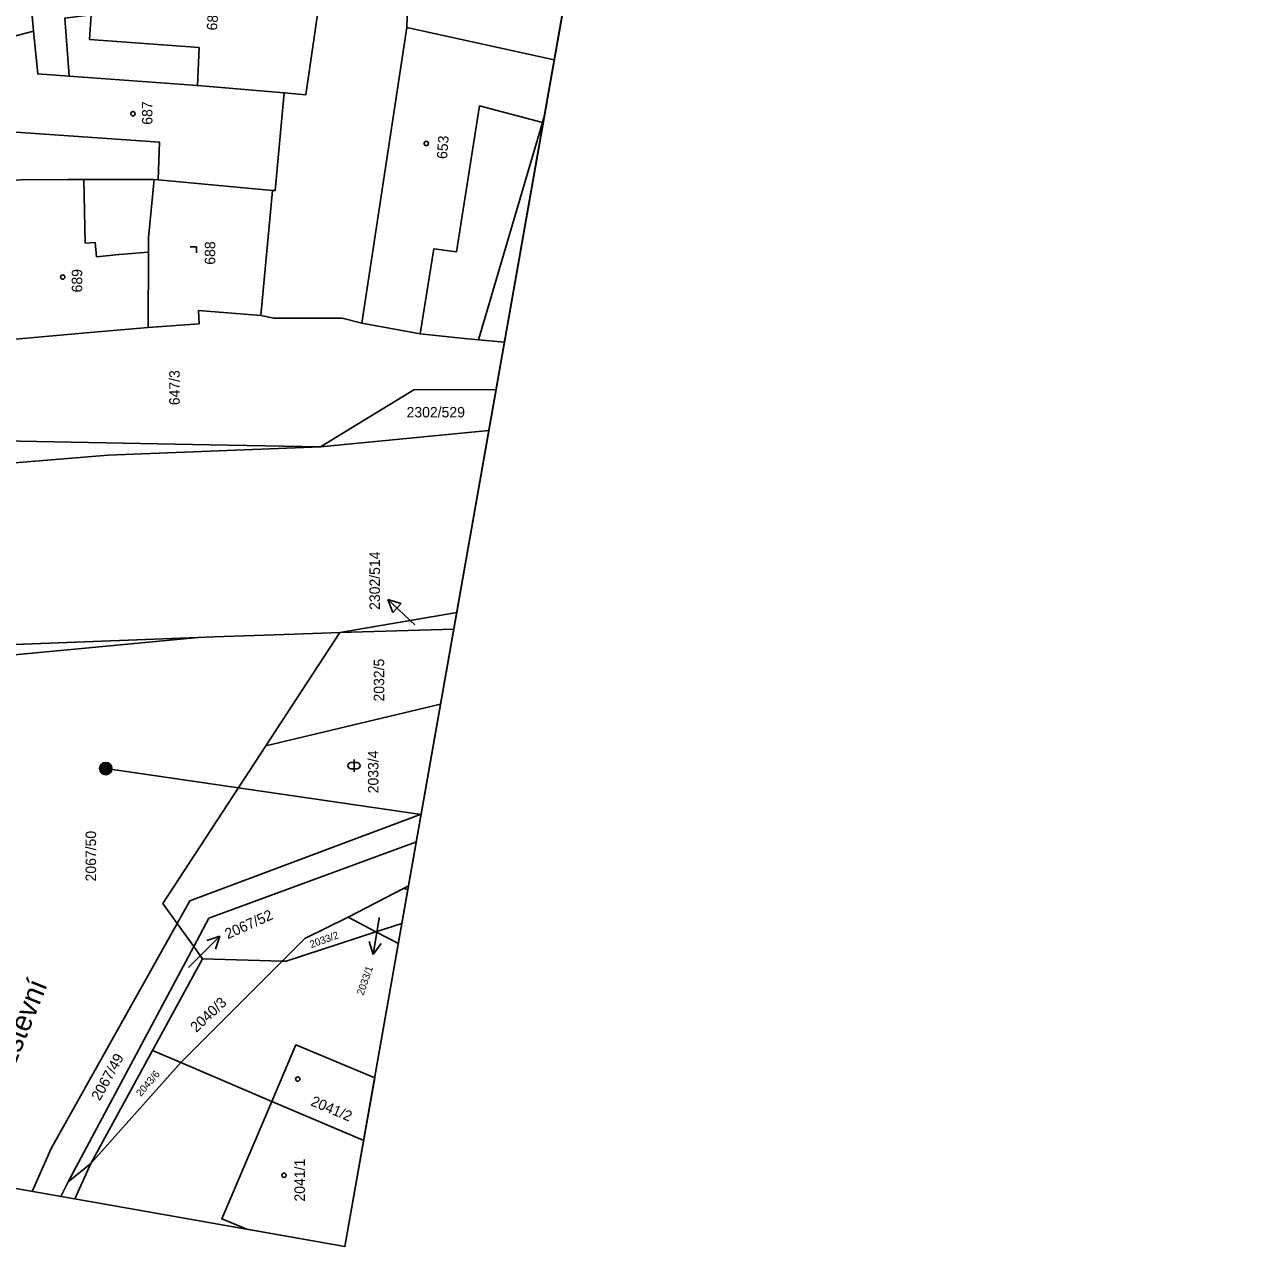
# Model space of a CAD drawing. Extents: x -534481 to -534262, y -1190577 to -1190138.
# Drawn here: x -534360.6 to -534261.7, y -1190577.1 to -1190477.8 of the extents above; entities that cross this region are included whole.
import ezdxf

# ---------------------------------------------------------------- set-up
doc = ezdxf.new("R2010")
doc.units = 0
for name, color, linetype in [('_KN_Povodí_Moravy', 7, 'Continuous'), ('_rámeček', 7, 'Continuous'), ('_rámeček_mřížka', 7, 'Continuous'), ('Hranice parcel', 7, 'Continuous'), ('Parcelní čísla', 7, 'Continuous'), ('Polygon budovy', 7, 'Continuous'), ('Pop  PČ popisy', 7, 'Continuous'), ('Poz předměty', 7, 'Continuous'), ('Značky budov', 7, 'Continuous'), ('Značky kultur', 7, 'Continuous')]:
    doc.layers.add(name, color=color, linetype=linetype)

msp = doc.modelspace()

# ---------------------------------------------------------------- linework, layer by layer
at = {"layer": '_KN_Povodí_Moravy'}
for p, q in [((-534322.907, -1190510.761), (-534336.58, -1190512.09)), ((-534325.515, -1190525.554), (-534322.907, -1190510.761)), ((-534330.718, -1190525.556), (-534331.106, -1190524.506)), ((-534331.106, -1190524.506), (-534330.033, -1190524.825)), ((-534330.376, -1190525.19), (-534330.375, -1190525.191)), ((-534381.269, -1190528.899), (-534346.53, -1190527.59))]:
    msp.add_line(p, q, dxfattribs=at)
for points in [[(-534336.58, -1190512.09), (-534345.56, -1190512.439), (-534353.84, -1190512.76), (-534368.41, -1190513.97)], [(-534330.375, -1190525.191), (-534330.718, -1190525.556)], [(-534330.033, -1190524.825), (-534330.376, -1190525.19)], [(-534335.01, -1190527.19), (-534329.294, -1190526.205), (-534328.987, -1190526.152), (-534325.515, -1190525.554)], [(-534346.53, -1190527.59), (-534345.23, -1190527.54), (-534338.73, -1190527.32), (-534335.01, -1190527.19)]]:
    msp.add_lwpolyline(points, dxfattribs=at)
at = {"layer": '_rámeček'}
for points in [[(-534407.912, -1190137.674), (-534480.845, -1190551.293), (-534334.601, -1190577.08), (-534261.668, -1190163.461)], [(-534480.845, -1190551.293), (-534334.601, -1190577.08), (-534316.367, -1190473.675)]]:
    msp.add_lwpolyline(points, dxfattribs=at)
at = {"layer": '_rámeček_mřížka'}
msp.add_lwpolyline([(-534480.845, -1190551.293), (-534334.601, -1190577.08), (-534261.668, -1190163.461)], dxfattribs=at)
at = {"layer": 'Hranice parcel'}
for p, q in [((-534360.35, -1190473.34), (-534359.92, -1190478.31)), ((-534359.92, -1190478.31), (-534363.23, -1190479.17)), ((-534329.58, -1190478.02), (-534333.24, -1190502.03)), ((-534317.593, -1190480.628), (-534329.58, -1190478.02)), ((-534318.55, -1190485.72), (-534318.46, -1190485.43)), ((-534318.411, -1190485.262), (-534318.46, -1190485.43)), ((-534323.74, -1190503.39), (-534318.55, -1190485.72)), ((-534340.49, -1190491.25), (-534341.45, -1190501.42)), ((-534323.74, -1190503.39), (-534321.639, -1190503.572)), ((-534335.01, -1190527.19), (-534341.03, -1190536.4)), ((-534346.53, -1190527.59), (-534363.09, -1190529.14)), ((-534341.03, -1190536.4), (-534326.83, -1190533.01)), ((-534341.03, -1190536.4), (-534349.4, -1190549.21)), ((-534329.84, -1190547.99), (-534334.33, -1190550.31)), ((-534329.485, -1190548.07), (-534329.84, -1190547.99)), ((-534349.4, -1190549.21), (-534348.24, -1190550.82)), ((-534348.24, -1190550.82), (-534346.89, -1190552.7)), ((-534332.09, -1190551.51), (-534334.33, -1190550.31)), ((-534329.971, -1190550.826), (-534332.09, -1190551.51)), ((-534332.09, -1190551.51), (-534330.259, -1190552.46)), ((-534357.1, -1190571.82), (-534346.89, -1190552.7)), ((-534346.89, -1190552.7), (-534346.17, -1190553.69)), ((-534346.17, -1190553.69), (-534350.25, -1190561.15)), ((-534339.7, -1190553.88), (-534347.95, -1190562.13)), ((-534346.17, -1190553.69), (-534339.7, -1190553.88)), ((-534350.25, -1190561.15), (-534355.26, -1190570.33)), ((-534347.95, -1190562.13), (-534350.25, -1190561.15)), ((-534347.95, -1190562.13), (-534355.26, -1190570.33)), ((-534340.55, -1190565.28), (-534347.95, -1190562.13)), ((-534333.081, -1190568.462), (-534340.55, -1190565.28)), ((-534355.26, -1190570.33), (-534357.1, -1190571.82)), ((-534355.26, -1190570.33), (-534356.54, -1190573.212)), ((-534357.68, -1190573.011), (-534357.1, -1190571.82))]:
    msp.add_line(p, q, dxfattribs=at)
for points in [[(-534329.58, -1190478.02), (-534329.52, -1190476.22), (-534329.36, -1190471.67), (-534329.3, -1190469.99)], [(-534336.54, -1190474.87), (-534337.79, -1190483.49), (-534339.53, -1190483.31)], [(-534359.92, -1190478.31), (-534359.56, -1190481.78), (-534357.01, -1190481.97), (-534346.59, -1190482.73), (-534339.53, -1190483.31)], [(-534339.53, -1190483.31), (-534340.26, -1190491.25), (-534340.49, -1190491.25)], [(-534318.46, -1190485.43), (-534318.442, -1190485.438)], [(-534360.94, -1190490.38), (-534357.12, -1190490.37), (-534355.82, -1190490.37), (-534352.77, -1190490.36), (-534350.1, -1190490.36)], [(-534350.1, -1190490.36), (-534350.56, -1190495.07), (-534350.57, -1190496.27), (-534350.6, -1190502.38)], [(-534350.1, -1190490.36), (-534349.79, -1190490.39), (-534340.49, -1190491.25)], [(-534350.6, -1190502.38), (-534346.45, -1190502.08), (-534346.49, -1190501), (-534341.45, -1190501.42)], [(-534341.45, -1190501.42), (-534340.38, -1190501.64), (-534334.84, -1190501.63), (-534333.24, -1190502.03)], [(-534361.66, -1190503.37), (-534355.33, -1190502.8), (-534350.6, -1190502.38)], [(-534333.24, -1190502.03), (-534328.48, -1190502.91), (-534324.65, -1190503.31), (-534323.74, -1190503.39)], [(-534336.58, -1190512.09), (-534329.01, -1190507.46), (-534322.321, -1190507.441)], [(-534372.58, -1190511.69), (-534370.92, -1190511.44), (-534345.58, -1190511.92), (-534336.58, -1190512.09)], [(-534322.907, -1190510.761), (-534336.58, -1190512.09)], [(-534336.58, -1190512.09), (-534353.84, -1190512.76), (-534368.41, -1190513.97)], [(-534335.01, -1190527.19), (-534325.515, -1190525.554)], [(-534346.53, -1190527.59), (-534345.23, -1190527.54), (-534338.73, -1190527.32), (-534335.01, -1190527.19)], [(-534325.756, -1190526.92), (-534335.01, -1190527.19)], [(-534381.269, -1190528.899), (-534346.53, -1190527.59)], [(-534348.24, -1190550.82), (-534347.22, -1190548.99), (-534328.402, -1190541.928)], [(-534346.89, -1190552.7), (-534345.66, -1190550.4), (-534328.801, -1190544.189)], [(-534329.431, -1190547.763), (-534329.84, -1190547.99)], [(-534348.24, -1190550.82), (-534358.48, -1190569.12), (-534360.013, -1190572.599)], [(-534334.33, -1190550.31), (-534337.86, -1190552.04), (-534339.7, -1190553.88)], [(-534332.09, -1190551.51), (-534339.39, -1190553.89), (-534339.7, -1190553.88)], [(-534332.182, -1190563.363), (-534338.6, -1190560.69), (-534340.55, -1190565.28)], [(-534340.55, -1190565.28), (-534344.61, -1190574.82), (-534342.564, -1190575.676)]]:
    msp.add_lwpolyline(points, dxfattribs=at)
at = {"layer": 'Polygon budovy'}
msp.add_line((-534318.411, -1190485.262), (-534317.593, -1190480.628), dxfattribs=at)
for points in [[(-534360.35, -1190473.34), (-534359.92, -1190478.31), (-534359.56, -1190481.78), (-534357.01, -1190481.97), (-534357.36, -1190477.25), (-534355.22, -1190476.99), (-534355.37, -1190478.98), (-534346.45, -1190479.65), (-534346.59, -1190482.73), (-534339.53, -1190483.31), (-534337.79, -1190483.49), (-534336.54, -1190474.87), (-534344.1, -1190474.27), (-534347.75, -1190473.84), (-534350.15, -1190473.56), (-534350.19, -1190473.9)], [(-534361.82, -1190486.07), (-534361.73, -1190486.49), (-534349.66, -1190487.33), (-534349.79, -1190490.39), (-534340.49, -1190491.25), (-534340.26, -1190491.25), (-534339.53, -1190483.31), (-534346.59, -1190482.73), (-534357.01, -1190481.97), (-534359.56, -1190481.78), (-534359.92, -1190478.31), (-534363.23, -1190479.17)], [(-534361.66, -1190503.37), (-534355.33, -1190502.8), (-534350.6, -1190502.38), (-534350.57, -1190496.27), (-534352.95, -1190496.47), (-534354.79, -1190496.64), (-534354.9, -1190495.48), (-534355.71, -1190495.55), (-534355.82, -1190490.37), (-534357.12, -1190490.37), (-534360.94, -1190490.38), (-534361.64, -1190490.44), (-534361.58, -1190496.28)]]:
    msp.add_lwpolyline(points, close=True, dxfattribs=at)
for points in [[(-534317.593, -1190480.628), (-534329.58, -1190478.02), (-534333.24, -1190502.03), (-534328.48, -1190502.91), (-534327.37, -1190495.99), (-534325.53, -1190496.23), (-534323.67, -1190484.39), (-534318.55, -1190485.72), (-534318.46, -1190485.43), (-534318.411, -1190485.262)], [(-534332.182, -1190563.363), (-534338.6, -1190560.69), (-534340.55, -1190565.28), (-534344.61, -1190574.82), (-534342.564, -1190575.676)], [(-534342.564, -1190575.676), (-534334.601, -1190577.08), (-534332.182, -1190563.363)]]:
    msp.add_lwpolyline(points, dxfattribs=at)
at = {"layer": 'Pop  PČ popisy'}
for p, q in [((-534328.917, -1190526.558), (-534331.106, -1190524.506)), ((-534331.106, -1190524.506), (-534330.033, -1190524.825)), ((-534331.106, -1190524.506), (-534330.718, -1190525.556)), ((-534331.83, -1190550.39), (-534332.299, -1190553.354)), ((-534331.82, -1190550.33), (-534331.83, -1190550.39)), ((-534346.89, -1190553.97), (-534344.768, -1190551.848)), ((-534344.768, -1190551.848), (-534345.83, -1190552.202)), ((-534344.768, -1190551.848), (-534345.122, -1190552.91)), ((-534332.299, -1190553.354), (-534332.637, -1190552.287)), ((-534332.299, -1190553.354), (-534331.648, -1190552.443)), ((-534347.32, -1190554.4), (-534346.89, -1190553.97))]:
    msp.add_line(p, q, dxfattribs=at)
at = {"layer": 'Poz předměty'}
msp.add_line((-534328.41, -1190541.97), (-534354.04, -1190538.24), dxfattribs=at)
for radius in [0.5, 0.4, 0.3, 0.2, 0.1]:
    msp.add_circle((-534354.043, -1190538.24), radius, dxfattribs=at)
at = {"layer": 'Značky budov'}
for centre in [(-534351.832, -1190485.022), (-534327.994, -1190487.438), (-534357.533, -1190498.294), (-534338.437, -1190563.469), (-534339.546, -1190571.286)]:
    msp.add_circle(centre, 0.175, dxfattribs=at)
at = {"layer": 'Značky kultur'}
for p, q in [((-534346.666, -1190495.83), (-534347.166, -1190495.83)), ((-534346.666, -1190496.33), (-534346.666, -1190495.83)), ((-534333.614, -1190537.753), (-534334.115, -1190537.753)), ((-534334.115, -1190538.254), (-534333.614, -1190538.254)), ((-534333.865, -1190538.504), (-534333.865, -1190537.503))]:
    msp.add_line(p, q, dxfattribs=at)
for centre, start, end in [((-534334.115, -1190538.004), 90, 270), ((-534333.615, -1190538.004), 270, 89.98789)]:
    msp.add_arc(centre, 0.25, start, end, dxfattribs=at)

# ---------------------------------------------------------------- texts
at = {"layer": 'Parcelní čísla'}
for s, height, rotation, p in [('686', 0.85, 86, (-534345.001, -1190478.275)), ('687', 0.85, 90, (-534350.247, -1190485.91)), ('653', 0.85, 86, (-534326.301, -1190488.717)), ('688', 0.85, 90, (-534345.14, -1190497.287)), ('689', 0.85, 90, (-534355.951, -1190499.539)), ('647/3', 0.85, 90, (-534348.031, -1190508.707)), ('2302/514', 0.85, 90, (-534331.759, -1190525.341)), ('2032/5', 0.85, 90, (-534331.412, -1190532.785)), ('2033/4', 0.85, 90, (-534331.883, -1190540.244)), ('2067/50', 0.85, 90, (-534354.826, -1190547.407)), ('2067/52', 0.85, 24, (-534344.129, -1190552.108)), ('2033/2', 0.595, 19.84606, (-534337.342, -1190552.833)), ('2033/1', 0.595, 71, (-534333.102, -1190556.707)), ('2040/3', 0.85, 43, (-534346.684, -1190559.725)), ('2067/49', 0.85, 61, (-534354.528, -1190565.295)), ('2043/6', 0.595, 49.41256, (-534351.182, -1190564.94)), ('2041/2', 0.85, 337, (-534337.452, -1190565.582)), ('2041/1', 0.85, 90, (-534337.856, -1190573.424))]:
    msp.add_text(s, height=height, rotation=rotation, dxfattribs=at).set_placement(p)
msp.add_text('2302/529', height=0.85, dxfattribs=at).set_placement((-534329.594, -1190509.699))
at = {"layer": 'Pop  PČ popisy'}
msp.add_text('Družstevní', height=1.7, rotation=68, dxfattribs=at).set_placement((-534362.807, -1190565.853))

doc.saveas('drawing.dxf')
